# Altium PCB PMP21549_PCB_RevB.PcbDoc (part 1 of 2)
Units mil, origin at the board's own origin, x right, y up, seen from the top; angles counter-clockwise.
Board outline 4798 x 2992 mil, 2 copper layers (Top Layer, Bottom Layer), stack 62 mil thick; 82 components, 39 nets, 178 pads, 21 vias.
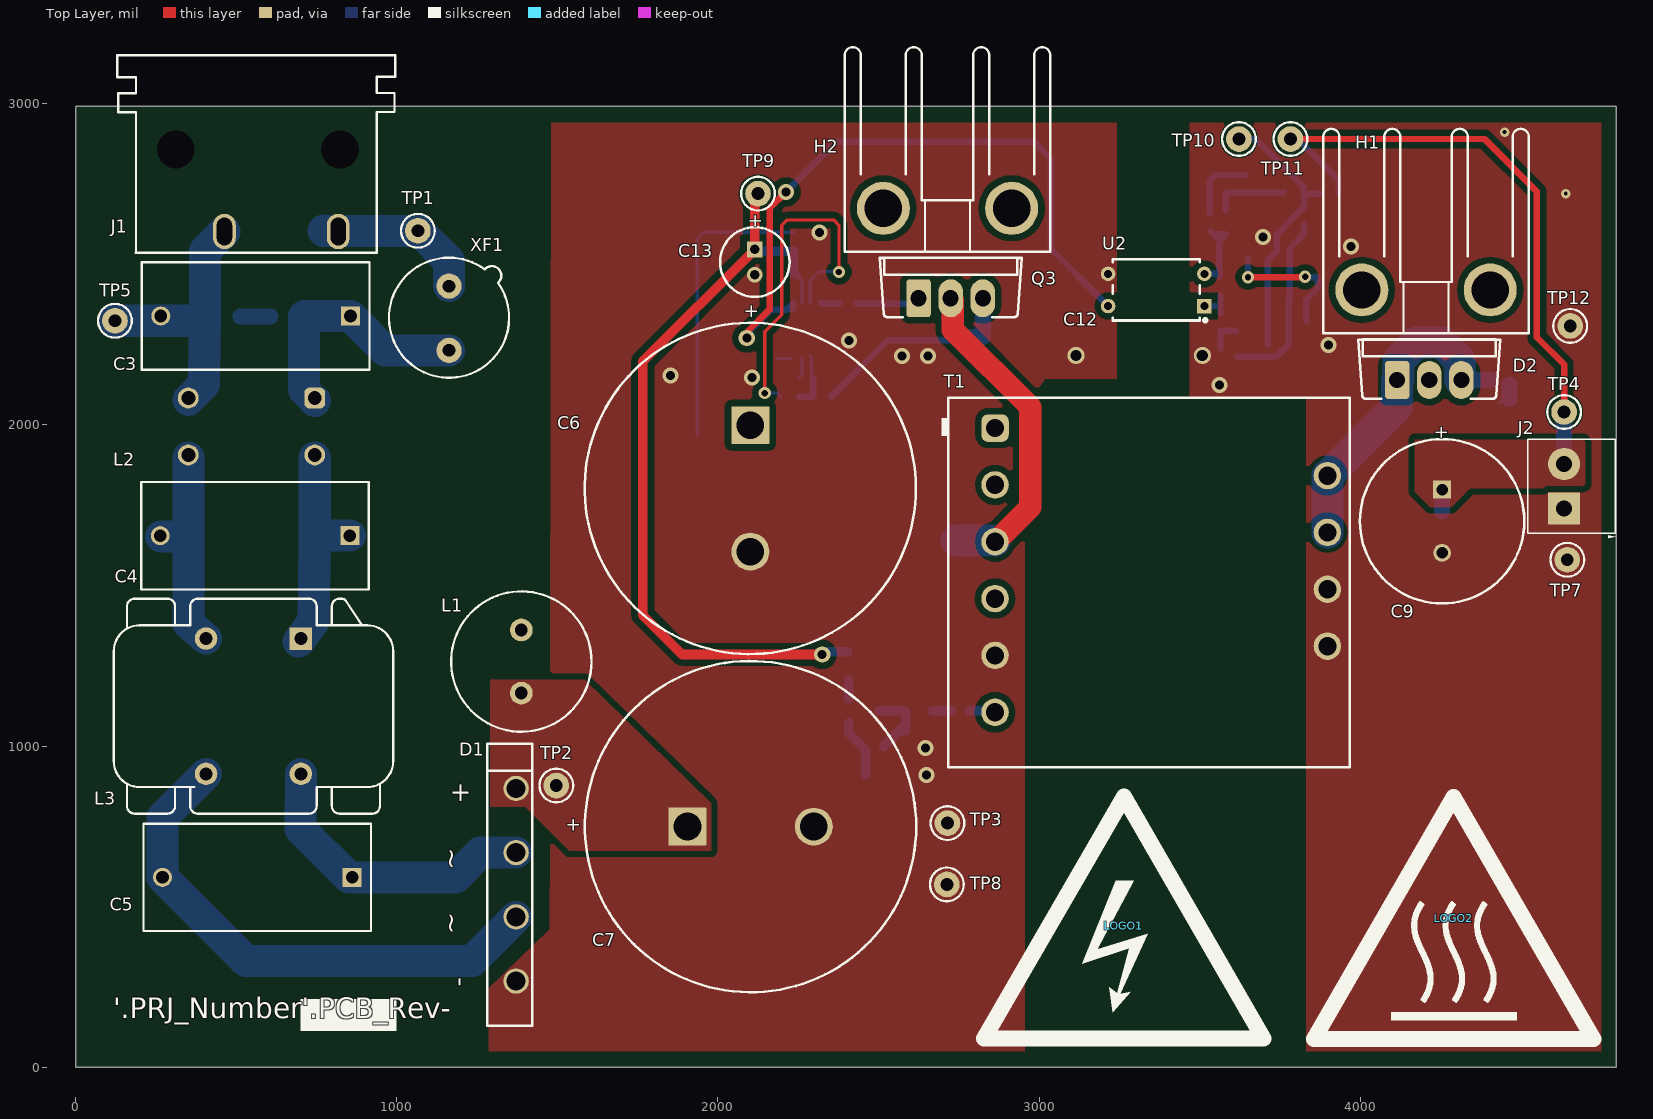
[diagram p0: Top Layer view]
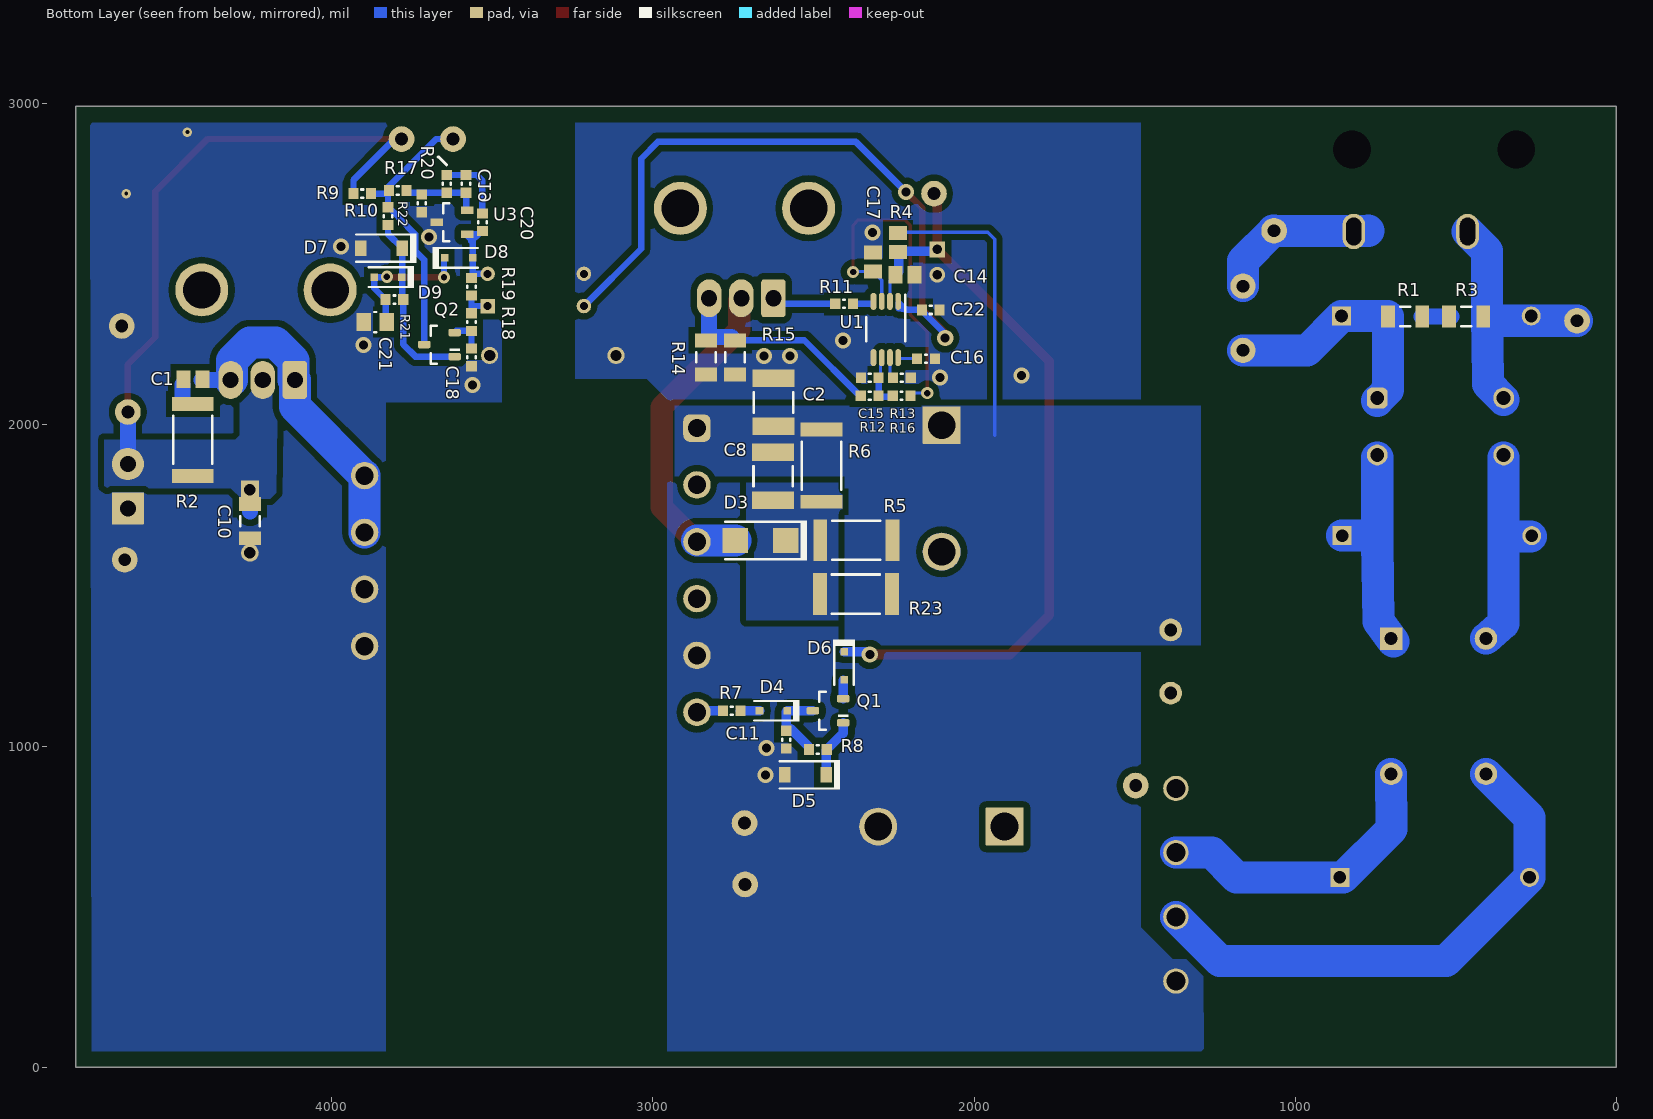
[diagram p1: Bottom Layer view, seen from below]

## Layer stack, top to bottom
Top Solder: solder mask 0.4, Solder Resist, Dk 3.5
Top Layer: signal copper 1.4
Dielectric1: core 59.2, FR-4, Dk 4.8
Bottom Layer: signal copper 1.4
Bottom Solder: solder mask 0.4, Solder Resist, Dk 3.5

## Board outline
0,0 4798,0 4798,2992 0,2992

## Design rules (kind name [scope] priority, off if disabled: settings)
AcuteAngle [All] p1: minimum=4.50000000000000E+0001 checktracksonly=FALSE
AssemblyTestPointUsage [All] p1: valid=2
Clearance Clearance_2 [InNetClass('HV') vs Not InNetClass('HV')] p1: gap=60 ignorepadtopadclearanceinfootprint=FALSE
Clearance Clearance_1 [InNetClass('MV') vs Not InNetClass('MV')] p2: gap=30 ignorepadtopadclearanceinfootprint=FALSE
Clearance Clearance_Keepouts [((IsTrack Or IsArc) And Not InPoly) And IsFree and IsKeepOut vs ((IsTrack Or IsArc) And Not InPoly) And IsFree and IsKeepOut] p3: gap=0 ignorepadtopadclearanceinfootprint=FALSE
Clearance Clearance_BoardEdge_MountingHoles [OnCopper and InComponentClass('Mounting Holes') vs IsKeepOut] p4: gap=40 ignorepadtopadclearanceinfootprint=FALSE except(0: Arc-Hole Track-Hole SMDPad-Hole THPad-Hole Via-Hole Fill-Hole Poly-Hole Region-Hole Text-Hole)
Clearance Clearance_BoardEdge_Poly [OnCopper and InPoly vs IsKeepOut] p5: gap=25 ignorepadtopadclearanceinfootprint=FALSE except(0: Arc-Hole Track-Hole SMDPad-Hole THPad-Hole Via-Hole Fill-Hole Poly-Hole Region-Hole Text-Hole)
Clearance Clearance_BoardEdge [OnCopper and Not InComponentClass('Logo') and not InComponentClass('FiducialMark') and not InRegion(1000,500,4000,800) and Not IsKeepout vs IsKeepOut] p6: gap=75 ignorepadtopadclearanceinfootprint=FALSE except(0: Arc-Hole Track-Hole SMDPad-Hole THPad-Hole Via-Hole Fill-Hole Poly-Hole Region-Hole Text-Hole)
Clearance Clearance_Poly [InPolygon] p7: gap=20 ignorepadtopadclearanceinfootprint=FALSE except(0: Arc-Hole Track-Hole SMDPad-Hole THPad-Hole Via-Hole Fill-Hole Poly-Hole Region-Hole Text-Hole)
Clearance [All] p8: gap=7.87 ignorepadtopadclearanceinfootprint=FALSE except(0: Arc-Hole Track-Hole SMDPad-Hole THPad-Hole Via-Hole Fill-Hole Poly-Hole Region-Hole Text-Hole)
ComponentClearance ComponentClearance_MountingHoles_FiducialMarks [InComponentClass('Mounting Holes') vs InComponentClass('FiducialMark')] p1: gap=20 collisioncheckmode=3 verticalgap=10 showdistances=FALSE
ComponentClearance ComponentClearance_Shunt [InComponentClass('Header') vs InComponentClass('Shunt')] p2: gap=0 collisioncheckmode=3 verticalgap=0 showdistances=FALSE
ComponentClearance ComponentClearance_Logo [InComponentClass('Logo')] p3: gap=5 collisioncheckmode=3 verticalgap=10 showdistances=FALSE
ComponentClearance ComponentClearance_ScrewToNut [(HasFootprint('NY PMS 440 0025 PH')) vs (HasFootprint('Keystone_1902C'))] p4: gap=20 collisioncheckmode=3 verticalgap=100000 showdistances=FALSE
ComponentClearance ComponentClearance_MountingHoles [InComponentClass('Mounting Holes')] p5: gap=20 collisioncheckmode=3 verticalgap=10 showdistances=FALSE
ComponentClearance ComponentClearance_SmallPassives [HasFootprint('0201*') or HasFootprint('0402*') or HasFootprint('0508') or HasFootprint('0603*') or HasFootprint('0612') or HasFootprint('0805*') or HasFootprint('0815*') or HasFootprint('0830*') or HasFootprint('1206*') or HasFootprint('1210*') or HasFootprint('1808*') or HasFootprint('1812*') or HasFootprint('1825*') or HasFootprint('2010*') or HasFootprint('2220*') or HasFootprint('2225*') or HasFootprint('2512*') or HasFootprint('2728*') or HasFootprint('3518*') vs HasFootprint('0201*') or HasFootprint('0402*') or HasFootprint('0508') or HasFootprint('0603*') or HasFootprint('0612') or HasFootprint('0805*') or HasFootprint('0815*') or HasFootprint('0830*') or HasFootprint('1206*') or HasFootprint('1210*') or HasFootprint('1808*') or HasFootprint('1812*') or HasFootprint('1825*') or HasFootprint('2010*') or HasFootprint('2220*') or HasFootprint('2225*') or HasFootprint('2512*') or HasFootprint('2728*') or HasFootprint('3518*')] p6: gap=20 collisioncheckmode=3 verticalgap=20 showdistances=FALSE
ComponentClearance ComponentClearance_THtoSMT [IsThruComponent vs IsSMTComponent] p7: gap=10 collisioncheckmode=3 verticalgap=10 showdistances=FALSE
ComponentClearance ComponentClearance_THtoTH [IsThruComponent vs IsThruComponent] p8: gap=10 collisioncheckmode=3 verticalgap=10 showdistances=FALSE
ComponentClearance [All] p9: gap=10 collisioncheckmode=3 verticalgap=10 showdistances=FALSE
DiffPairsRouting [All] p1: maxlimit=100 minlimit=10 mostfreqgap=10 toplayer_minwidth=15 toplayer_maxwidth=15 toplayer_prefwidth=15 bottomlayer_minwidth=15 bottomlayer_maxwidth=15 bottomlayer_prefwidth=15 maxuncoupledlength=1000
FabricationTestPointUsage TestPointUsage [All] p1: valid=2 allowmultiple=FALSE
FabricationTestpoint Testpoint [All] p1: side=3 testpointundercomponent=TRUE minsize=40 maxsize=100 preferedsize=60 minholesize=0 maxholesize=40 preferedholesize=32 testpointgrid=1 allowsidetop=TRUE allowsidebottom=TRUE usegrid=TRUE gridtolerance=0.01
FanoutControl Fanout_LCC [IsLCC] p1: bgadir=Out bgaviamode=Centered fanoutstyle=Auto fanoutdirection=Alternating viagrid=1 // Fanout_LCC (Default Rule)
FanoutControl Fanout_BGA [IsBGA] p2: bgadir=Out bgaviamode=Centered fanoutstyle=Auto fanoutdirection=Alternating viagrid=1 // Fanout_BGA (Default Rule)
FanoutControl Fanout_Default [All] p4: bgadir=Out bgaviamode=Centered fanoutstyle=Auto fanoutdirection=Alternating viagrid=1 // Fanout_Default (Default Rule)
FanoutControl Fanout_Small [(CompPinCount < 5)] p5: bgadir=Out bgaviamode=Centered fanoutstyle=Auto fanoutdirection=OutThenIn viagrid=1 // Fanout_Small (Default Rule)
Height [All] p1: minheight=0 maxheight=3000 prefheight=500
HoleSize [All] p1: absolutevalues=TRUE maxlimit=251 minlimit=7 maxpercent=80.000 minpercent=20.000
MinimumAnnularRing MinimumAnnularRing_ThermalPadVias [IsVia and InAnyComponent] p1: minimumring=5.91
MinimumAnnularRing [All] p2: minimumring=4.9
MinimumSolderMaskSliver MinimumSolderMaskSliver_Logo [InComponentClass('Logo') vs InComponentClass('Logo')] p1: minsoldermaskwidth=0.7
MinimumSolderMaskSliver [All] p2: minsoldermaskwidth=2
PlaneConnect [All] p1: planeconnectstyle=Direct reliefexpansion=10 reliefentries=4 reliefconductorwidth=10 reliefairgap=10
PolygonConnect PolygonConnect_15 [All vs IsNamedPolygon('C109_2') Or  IsNamedPolygon('C107_2') Or  IsNamedPolygon('HV') Or  IsNamedPolygon('Q203_5') Or  IsNamedPolygon('C107_2') Or  IsNamedPolygon('HS') Or  IsNamedPolygon('Q201_5') Or  IsNamedPolygon('Q203_5') Or  IsNamedPolygon('C106_2') Or  IsNamedPolygon('C108_2') Or  IsNamedPolygon('Vout') Or  IsNamedPolygon('Q203_5') Or  IsNamedPolygon('C108_2') Or  IsNamedPolygon('C113_2') Or  IsNamedPolygon('Q203_5') Or  IsNamedPolygon('Q201_5') Or  IsNamedPolygon('C107_2') Or  IsNamedPolygon('C102_1') Or  IsNamedPolygon('SGND') Or  IsNamedPolygon('GND') Or  IsNamedPolygon('SGND') Or  IsNamedPolygon('GND') Or  IsNamedPolygon('IN+') Or  IsNamedPolygon('IN+') Or  IsNamedPolygon('Q201_5') Or  IsNamedPolygon('Q201_5') Or  IsNamedPolygon('SGND') Or  IsNamedPolygon('SGND') Or  IsNamedPolygon('Vout') Or  IsNamedPolygon('Vout') Or  IsNamedPolygon('IN+') Or  IsNamedPolygon('GND') Or  IsNamedPolygon('IN+') Or  IsNamedPolygon('GND')] p1: connectstyle=Direct reliefconductorwidth=10 reliefentries=4 polygonreliefangle="90 Angle" airgapwidth=10
PolygonConnect PolygonConnect_14 [All vs IsNamedPolygon('C106_2') Or  IsNamedPolygon('C107_2') Or  IsNamedPolygon('C107_2') Or  IsNamedPolygon('C107_2') Or  IsNamedPolygon('C102_1') Or  IsNamedPolygon('Q203_5') Or  IsNamedPolygon('Vout') Or  IsNamedPolygon('Q203_5') Or  IsNamedPolygon('Q203_5') Or  IsNamedPolygon('Q201_5') Or  IsNamedPolygon('C108_2') Or  IsNamedPolygon('Q203_5') Or  IsNamedPolygon('HS') Or  IsNamedPolygon('HV') Or  IsNamedPolygon('C108_2') Or  IsNamedPolygon('Q201_5') Or  IsNamedPolygon('C109_2') Or  IsNamedPolygon('Q201_5') Or  IsNamedPolygon('Q201_5') Or  IsNamedPolygon('C113_2')] p2: connectstyle=Direct reliefconductorwidth=10 reliefentries=4 polygonreliefangle="90 Angle" airgapwidth=10
PolygonConnect PolygonConnect_13 [All vs IsNamedPolygon('C102_1') Or  IsNamedPolygon('HV') Or  IsNamedPolygon('C107_2') Or  IsNamedPolygon('C109_2') Or  IsNamedPolygon('C107_2') Or  IsNamedPolygon('C108_2') Or  IsNamedPolygon('C106_2') Or  IsNamedPolygon('C108_2') Or  IsNamedPolygon('C113_2') Or  IsNamedPolygon('C107_2')] p3: connectstyle=Direct reliefconductorwidth=10 reliefentries=4 polygonreliefangle="90 Angle" airgapwidth=10
PolygonConnect PolygonConnect_12 [All vs IsNamedPolygon('C107_2') Or  IsNamedPolygon('C113_2') Or  IsNamedPolygon('C106_2') Or  IsNamedPolygon('C107_2') Or  IsNamedPolygon('C107_2') Or  IsNamedPolygon('C102_1')] p4: connectstyle=Direct reliefconductorwidth=10 reliefentries=4 polygonreliefangle="90 Angle" airgapwidth=10
PolygonConnect PolygonConnect_11 [All vs IsNamedPolygon('C106_2') Or  IsNamedPolygon('C102_1') Or  IsNamedPolygon('C107_2') Or  IsNamedPolygon('C107_2') Or  IsNamedPolygon('C107_2')] p5: connectstyle=Direct reliefconductorwidth=10 reliefentries=4 polygonreliefangle="90 Angle" airgapwidth=10
PolygonConnect PolygonConnect_10 [All vs IsNamedPolygon('C106_2')] p6: connectstyle=Direct reliefconductorwidth=10 reliefentries=4 polygonreliefangle="90 Angle" airgapwidth=10
PolygonConnect PolygonConnect_9 [All vs IsNamedPolygon('C11_1') Or  IsNamedPolygon('Vin') Or  IsNamedPolygon('Vin') Or  IsNamedPolygon('5V') Or  IsNamedPolygon('D6_2') Or  IsNamedPolygon('Q3_3') Or  IsNamedPolygon('GND2') Or  IsNamedPolygon('GND2') Or  IsNamedPolygon('GND') Or  IsNamedPolygon('Q3_4') Or  IsNamedPolygon('12V5') Or  IsNamedPolygon('GND') Or  IsNamedPolygon('12V5') Or  IsNamedPolygon('D3_1')] p7: connectstyle=Direct reliefconductorwidth=10 reliefentries=4 polygonreliefangle="90 Angle" airgapwidth=10
PolygonConnect PolygonConnect_8 [All vs IsNamedPolygon('C11_1') Or  IsNamedPolygon('Vin') Or  IsNamedPolygon('12V5') Or  IsNamedPolygon('Q3_3') Or  IsNamedPolygon('GND2') Or  IsNamedPolygon('GND2') Or  IsNamedPolygon('5V') Or  IsNamedPolygon('Q3_4') Or  IsNamedPolygon('12V5')] p8: connectstyle=Direct reliefconductorwidth=10 reliefentries=4 polygonreliefangle="90 Angle" airgapwidth=10
PolygonConnect PolygonConnect_7 [All vs IsNamedPolygon('GND2') Or  IsNamedPolygon('GND2') Or  IsNamedPolygon('5V') Or  IsNamedPolygon('12V5') Or  IsNamedPolygon('12V5') Or  IsNamedPolygon('C11_1')] p9: connectstyle=Direct reliefconductorwidth=10 reliefentries=4 polygonreliefangle="90 Angle" airgapwidth=10
PolygonConnect PolygonConnect_6 [All vs IsNamedPolygon('GND2') Or  IsNamedPolygon('SGND') Or  IsNamedPolygon('GND1') Or  IsNamedPolygon('C901_1') Or  IsNamedPolygon('SGND') Or  IsNamedPolygon('GND2') Or  IsNamedPolygon('GND1')] p10: connectstyle=Direct reliefconductorwidth=10 reliefentries=4 polygonreliefangle="90 Angle" airgapwidth=10
PolygonConnect PolygonConnect_5 [All vs IsNamedPolygon('GND1') Or  IsNamedPolygon('GND1')] p11: connectstyle=Direct reliefconductorwidth=10 reliefentries=4 polygonreliefangle="90 Angle" airgapwidth=10
PolygonConnect PolygonConnect_4 [All vs IsNamedPolygon('C21_1') Or  IsNamedPolygon('C5_1') Or  IsNamedPolygon('C12_2') Or  IsNamedPolygon('C2_2') Or  IsNamedPolygon('C13_1') Or  IsNamedPolygon('C28_1') Or  IsNamedPolygon('C6_1') Or  IsNamedPolygon('GND') Or  IsNamedPolygon('GND2') Or  IsNamedPolygon('C14_1') Or  IsNamedPolygon('C13_1') Or  IsNamedPolygon('Q1_3') Or  IsNamedPolygon('C14_1') Or  IsNamedPolygon('C5_1') Or  IsNamedPolygon('GND2') Or  IsNamedPolygon('C28_1') Or  IsNamedPolygon('D5_2') Or  IsNamedPolygon('D6_2') Or  IsNamedPolygon('D2_1') Or  IsNamedPolygon('C12_2') Or  IsNamedPolygon('D2_1') Or  IsNamedPolygon('C4_1') Or  IsNamedPolygon('C4_1') Or  IsNamedPolygon('C2_2') Or  IsNamedPolygon('GND') Or  IsNamedPolygon('C33_1') Or  IsNamedPolygon('C9_1')] p12: connectstyle=Direct reliefconductorwidth=10 reliefentries=4 polygonreliefangle="90 Angle" airgapwidth=10
PolygonConnect PolygonConnect_3 [All vs IsNamedPolygon('C28_1') Or  IsNamedPolygon('C12_2') Or  IsNamedPolygon('C28_1') Or  IsNamedPolygon('C9_1') Or  IsNamedPolygon('D5_2') Or  IsNamedPolygon('C12_2') Or  IsNamedPolygon('C2_2') Or  IsNamedPolygon('C14_1') Or  IsNamedPolygon('C4_1') Or  IsNamedPolygon('C14_1') Or  IsNamedPolygon('D6_2') Or  IsNamedPolygon('GND2') Or  IsNamedPolygon('Q1_3') Or  IsNamedPolygon('C5_1') Or  IsNamedPolygon('D2_1') Or  IsNamedPolygon('C4_1') Or  IsNamedPolygon('C13_1') Or  IsNamedPolygon('C5_1') Or  IsNamedPolygon('C13_1') Or  IsNamedPolygon('C33_1') Or  IsNamedPolygon('D2_1') Or  IsNamedPolygon('GND') Or  IsNamedPolygon('GND') Or  IsNamedPolygon('GND2') Or  IsNamedPolygon('C2_2') Or  IsNamedPolygon('C6_1') Or  IsNamedPolygon('C21_1')] p13: connectstyle=Direct reliefconductorwidth=10 reliefentries=4 polygonreliefangle="90 Angle" airgapwidth=10
PolygonConnect PolygonConnect_2 [All vs IsNamedPolygon('C21_1') Or  IsNamedPolygon('C4_1') Or  IsNamedPolygon('D5_2') Or  IsNamedPolygon('C5_1') Or  IsNamedPolygon('C14_1') Or  IsNamedPolygon('C13_1') Or  IsNamedPolygon('C4_1') Or  IsNamedPolygon('C33_1') Or  IsNamedPolygon('C12_2') Or  IsNamedPolygon('D2_1') Or  IsNamedPolygon('C2_2') Or  IsNamedPolygon('C28_1') Or  IsNamedPolygon('C12_2') Or  IsNamedPolygon('D2_1') Or  IsNamedPolygon('C5_1') Or  IsNamedPolygon('Q1_3') Or  IsNamedPolygon('GND') Or  IsNamedPolygon('D6_2') Or  IsNamedPolygon('C6_1') Or  IsNamedPolygon('C2_2') Or  IsNamedPolygon('C14_1') Or  IsNamedPolygon('C28_1') Or  IsNamedPolygon('C13_1') Or  IsNamedPolygon('C9_1') Or  IsNamedPolygon('GND')] p14: connectstyle=Direct reliefconductorwidth=10 reliefentries=4 polygonreliefangle="90 Angle" airgapwidth=10
PolygonConnect PolygonConnect_1 [All vs IsNamedPolygon('C28_1') Or  IsNamedPolygon('D5_2') Or  IsNamedPolygon('C5_1') Or  IsNamedPolygon('C5_1') Or  IsNamedPolygon('D2_1') Or  IsNamedPolygon('C21_1') Or  IsNamedPolygon('C9_1') Or  IsNamedPolygon('C4_1') Or  IsNamedPolygon('C14_1') Or  IsNamedPolygon('C28_1') Or  IsNamedPolygon('C6_1') Or  IsNamedPolygon('C12_2') Or  IsNamedPolygon('C33_1') Or  IsNamedPolygon('C4_1') Or  IsNamedPolygon('C13_1') Or  IsNamedPolygon('C12_2') Or  IsNamedPolygon('D6_2') Or  IsNamedPolygon('C2_2') Or  IsNamedPolygon('C14_1') Or  IsNamedPolygon('D2_1') Or  IsNamedPolygon('C2_2') Or  IsNamedPolygon('C13_1')] p15: connectstyle=Direct reliefconductorwidth=10 reliefentries=4 polygonreliefangle="90 Angle" airgapwidth=10
PolygonConnect [All] p16: connectstyle=Direct reliefconductorwidth=10 reliefentries=4 polygonreliefangle="90 Angle" airgapwidth=10
RoutingVias ThermalPadVias [IsVia and InAnyComponent] p1: holewidth=7.87 width=19.68 viastyle="Through Hole" minholewidth=7.87 minwidth=19.68 maxholewidth=12.99 maxwidth=23.62
RoutingVias [All] p2: holewidth=16 width=34 viastyle="Through Hole" minholewidth=7.87 minwidth=20 maxholewidth=40 maxwidth=65
SilkToBoardRegionClearance [Not ((IsComment or IsDesignator) And (Hide <> 'False')) and not InRegion(1000,500,4000,800)] p1:
SilkToSilkClearance SilkToSilkClearance_Pb-FreeLogo [(HasFootprint('Pb-Free_Overlay_Medium') OR HasFootprint('Pb-Free_Overlay_Small')) vs (HasFootprint('Pb-Free_Overlay_Medium') OR HasFootprint('Pb-Free_Overlay_Small'))] p1: silktosilkclearance=0
SilkToSilkClearance [All] p2: silktosilkclearance=1
SilkToSolderMaskClearance "Silk to Solder Mask Opening" [All] p1: minsilkscreentomaskgap=1 clearancetoexposedcopper=FALSE
SolderMaskExpansion [All] p1: expansion=1.97
Width [All] p1: maxlimit=100 minlimit=6 preferedwidth=10 checkconnectedcopper=TRUE
14 further rules are at their usual default settings.

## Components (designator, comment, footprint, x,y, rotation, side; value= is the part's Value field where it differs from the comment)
C1 "GRM21AR72E222KW01D" 0805L 4432.47,2142 r180 bottom value=2200pF
C2 "GRM43DR72J104KW01L" 1812L 2625,2070 r90 bottom value=0.1uF
C3 "B32922C3334K" B32922_14.5mm 560.72,2339 r180 top value=0.33uF
C4 "B32922C3334K" B32922_14.5mm 559,1655 r180 top value=0.33uF
C5 "B32922C3334K" B32922_14.5mm 566,591 r180 top value=0.33uF
C6 "LLS2G121MELA" Nichicon_2500x2500_Snap 2101,1802 r270 top value=120uF
C7 "LLS2G121MELA" Nichicon_2500x2500_Snap 2101.85,749 r0 top value=120uF
C8 "GRM43DR72J104KW01L" 1812L 2626,1840 r270 bottom value=0.1uF
C9 "EEU-FR1V102B" FR_1250x2000 4255,1700 r270 top value=1000uF
C10 "C3216X7R1V106K160AC" 1206_180L 4255,1700 r270 bottom value=10uF
C11 "0603YC104JAT2A" 0603L 2585,1020 r270 bottom value=0.1uF
C12 "DE1E3RA222MN4AN01F" DE1_900x400 3312,2216 r180 top value=2200pF
C13 "35ZLJ47MTA5X11" ZLJ_500x1100 2115,2507.01 r270 top value=47uF
C14 "08053D474KAT2A" 0805L 2215,2467.01 r180 bottom value=0.47uF
C15 "06035A271JAT2A" 0603L 2325,2147.01 r0 bottom value=270pF
C16 "C1608X7R1H474K080AC" 0603L 2150,2206 r180 bottom value=0.47uF
C17 "0805YC474JAT2A" 0805L 2315,2507.01 r90 bottom value=0.47uF
C18 "C0603C104J3RACTU" 0603L 3565,2210 r270 bottom value=0.1uF
C19 "C0603C104J3RACTU" 0603L 3582.2,2750.31 r90 bottom value=0.1uF
C20 "C0603X223K5RACTU" 0603L 3531,2631 r270 bottom value=0.022uF
C21 "08053C225KAT2A" 0805_150 3865,2320 r0 bottom value=2.2uF
C22 "06035A101FAT2A" 0603L 2135,2358 r180 bottom value=100pF
D1 "GBU4J-BP" GBU 1372,568 r270 top value=600V
D2 "MBR20200CTTU" TO-220AB 4215,2140 r0 top value=200V
D3 "es1MTR" SMA 2665,1640 r0 bottom value=1000V
D4 "BAS316,115" SOD-323 2625,1110 r0 bottom value=100V
D5 "MMSZ4699T1G" SOD-123 2525,910 r0 bottom value=12V
D6 "BAS316,115" SOD-323 2405,1250 r270 bottom value=100V
D7 "MMSZ5235B-7-F" SOD-123 3845,2550 r0 bottom value=6.8V
D8 "BAS316,115" SOD-323 3605,2520 r180 bottom value=100V
D9 "BAS316,115" SOD-323 3825,2460 r0 bottom value=100V
H1 "634-10ABPE" HSINK_634-10ABP 4205,2420 r0 top
H2 "634-10ABPE" HSINK_634-10ABP 2715,2674.2 r0 top
J1 "770W-X2/10" CONN_AC_770W-SERIES 568,2732 r0 top
J2 "ED555/2DS" TERM_BLK_ED555-2DS 4635,1740 r90 top
L1 "7447471470" WE-TIS-1111 1388,1263 r90 top value=47uH
L2 "744841330" WE-CMB-NiZn-XS 548,1995 r270 top value=30uH
L3 "744823422" WE-CMB_M 554,1124 r270 top value=2.2mH
LOGO1 "DANGER HIGH VOLTAGE" IEC_HighVoltage_Large 3264,441 r0 top
LOGO2 "CAUTION HOT SURFACE" IEC_HotSurface_Large 4291,463 r0 top
Q1 "MMBT3904-7-F" SOT-23 2455,1110 r0 bottom value="40 V"
Q2 "MMBT3904-7-F" SOT-23 3665,2250 r0 bottom value="40 V"
Q3 "SPP17N80C3XKSA1" TO-220AB 2725,2394.2 r0 top value=800V
R1 "CRCW1206499KFKEA" 1206L 657.85,2337 r0 bottom value=499k
R2 "CRCW251220R0FKEG" 2512L 4432.82,1953 r90 bottom value=20.0
R3 "CRCW1206499KFKEA" 1206L 467.85,2337 r0 bottom value=499k
R4 "CRCW0805255KFKEA" 0805L 2236.84,2568 r90 bottom value=255k
R5 "CRCW2512110KJNEG" 2512L 2366.86,1641 r180 bottom value=110k
R6 "CRCW2512110KJNEG" 2512L 2475.37,1872.87 r90 bottom value=110k
R7 "CRCW060310R0FKEA" 0603L 2755,1110 r180 bottom value=10.0
R8 "CRCW060324K9FKEA" 0603L 2486.54,989 r0 bottom value=24.9k
R9 "RMCF0603ZT0R00" 0603L 3905,2720 r0 bottom value=0
R10 "CRCW06035K11FKEA" 0603L 3825,2650 r90 bottom value=5.11k
R11 "CRCW060310R0FKEA" 0603L 2405,2376.7 r0 bottom value=10.0
R12 "RT0603DRE071K07L" 0603L 2325.54,2091 r0 bottom value=1.07k
R13 "CRCW060360K4FKEA" 0603L 2225,2147.01 r0 bottom value=60.4k
R14 "ERJ-8BWFR100V" 1206L 2835,2210 r90 bottom value=0.1
R15 "ERJ-8BWFR100V" 1206L 2745,2210 r90 bottom value=0.1
R16 "CPF0603B100KE" 0603L 2226,2091 r0 bottom value=100k
R17 "RG1608P-2552-B-T5" 0603L 3795,2730 r0 bottom value=25.5k
R18 "CRCW06031K00FKEA" 0603L 3565,2320 r270 bottom value=1.00k
R19 "CRCW06031K00FKEA" 0603L 3565,2430 r270 bottom value=1.00k
R20 "ERJ-3EKF1002V" 0603L 3642.2,2750.31 r270 bottom value=10.0k
R21 "CRCW0603100KFKEA" 0603L 3805,2390 r180 bottom value=100k
R22 "CRCW06032K49FKEA" 0603L 3720,2689.56 r90 bottom value=2.49k
R23 "CRCW2512110KJNEG" 2512L 2368.14,1473 r180 bottom value=110k
T1 "RLTI-1260" Renco_RLTI-1260 3342,1509 r0 top value=1.05mH
TP1 "5000" Keystone5000 1066,2604.25 r90 top
TP2 "5000" Keystone5000 1497,877 r90 top
TP3 "5001" Keystone5001 2715,760 r90 top
TP4 "5000" Keystone5000 4635,2040 r90 top
TP5 "5000" Keystone5000 122.76,2324.25 r90 top
TP7 "5001" Keystone5001 4645,1580 r90 top
TP8 "5001" Keystone5001 2713,569 r90 top
TP9 "5000" Keystone5000 2125,2720 r90 top
TP10 "5000" Keystone5000 3622.6,2890 r90 top
TP11 "5000" Keystone5000 3783,2890 r90 top
TP12 "5001" Keystone5001 4654,2308 r90 top
U1 "LM5021MM-1/NOPB" DGK0008A_N 2275,2297.01 r270 bottom
U2 "FOD817A" DIP-4 3365,2420 r180 top
U3 "TL431AIDBZT" DBZ0003A_N 3626,2631 r0 bottom
XF1 "56000001009" FuseHolder_560000010 1163,2332 r90 top value=TR5

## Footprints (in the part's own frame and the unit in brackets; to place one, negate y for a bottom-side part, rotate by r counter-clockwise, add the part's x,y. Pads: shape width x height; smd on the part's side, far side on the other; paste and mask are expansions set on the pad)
0603L [mm] "0603 from SM-752 data"
  rect 0.8x0.85 smd: 1(-0.7,0) 2(0.7,0)
  silkscreen extent -0.07,-0.33 0.07,0.33, body extent -0.87,-0.47 0.87,0.47, height 1
0805_150 [mm] "0805 / 1.5 mm height"
  rect 1.15x1.45 smd: 1(-0.9,0) 2(0.9,0)
  silkscreen extent -0.1,-0.8 0.1,0.8, body extent -1.1,-0.72 1.1,0.72, height 1.5
0805L [mm] "0805 from SM-752 data"
  rect 1.1x1.4 smd: 1(-0.75,0) 2(0.75,0)
  body extent -1.1,-0.72 1.1,0.72, height 1.45
1206_180L [mm] "1206_180"
  rect 1.1x1.75 smd: 1(-1.35,0) 2(1.35,0)
  silkscreen extent -0.4,-0.77 0.4,0.77, body extent -1.75,-0.95 1.75,0.95, height 1.8
1206L [mm] "1206 from SM-752 data"
  rect 1.1x1.75 smd: 1(-1.35,0) 2(1.35,0)
  silkscreen extent -0.4,-0.77 0.4,0.77, body extent -1.7,-0.9 1.7,0.9, height 1.35
1812L [mm]
  rect 1.4x3.3 smd: 1(-1.9,0) 2(1.9,0)
  silkscreen extent -0.8,-1.55 0.8,1.55, body extent -2.4,-1.7 2.4,1.7, height 1.35
2512L [mm] "Chip Resistor, Body 6.3x3.2mm, IPC High Density"
  rect 1.1x3.3 smd: 1(-2.85,0) 2(2.85,0)
  silkscreen extent -1.9,-1.55 1.9,1.55, body extent -3.22,-1.67 3.22,1.67, height 0.71
B32922_14.5mm [mm] "Epcos film capacitors, 15mm spacing"
  rect 1.5x1.5 hole 1: 1(-7.5,0)
  round 1.5 hole 1: 2(7.5,0)
  silkscreen extent -9,-4.25 9,4.25, body extent -9,-4.25 9,4.25, height 14.5
CONN_AC_770W-SERIES [mm] "Qualtek Electronics"
  oval 1.8x2.8 hole 1.2 slot 2.2 at 90 deg: 1(6.35,-3.3) 2(-2.65,-3.3)
  round 2 hole 3 unplated: MH1(6.5,3.2) MH2(-6.5,3.2)
  silkscreen extent -11.12,-4.97 10.87,10.63, body extent -11.05,-4.8 10.8,10.6, height 22
DBZ0003A_N [mm] "SOT23, 3-Leads, Body 2.9x1.3mm, Pitch 0.95mm, Lead Span 2.4mm, IPC Medium Density"
  rrect17% 1x0.6 smd: 1(-1.2,0.95) 2(-1.2,-0.95) 3(1.2,0)
  silkscreen extent 0.2,-1.5 0.7,1.5, body extent -1.26,-1.46 1.26,1.46, height 0.98
DE1_900x400 [mm] "TH, 2-Leads, Dia 9mm, Lead Spacing 10mm"
  round 1.35 hole 0.9: 1(-5,0) 2(5,0)
  body extent -5.3,-2 5.3,2, height 11.5
DGK0008A_N [mm] "TSOP, 8-Leads, Body 3x3mm, Pitch 0.65mm, IPC Medium Density"
  oval 1.35x0.45 smd: 1(-2.225,0.975) 2(-2.225,0.325) 3(-2.225,-0.325) 4(-2.225,-0.975) 5(2.225,-0.975) 6(2.225,-0.325) 7(2.225,0.325) 8(2.225,0.975)
  silkscreen extent -2.75,-1.55 0.95,1.55, body extent -2.45,-1.5 2.45,1.5, height 0.96
DIP-4 [mm] "DIP, 4-Leads, Body 6.86x4.83mm, Pitch 2.54mm"
  rect 1.15x1.15 hole 0.65: 1(-3.81,1.27)
  round 1.15 hole 0.65: 2(-3.81,-1.27) 3(3.81,-1.27) 4(3.81,1.27)
  silkscreen extent -4,-2.41 3.43,2.52, body extent -4.02,-2.41 4.02,2.41, height 5.59
FR_1250x2000 [mm] "TH, 2-Leads, Dia 12.5mm, Lead Spacing 5mm"
  rect 1.4x1.4 hole 0.9: 1(-2.5,0)
  round 1.4 hole 0.9: 2(2.5,0)
  silkscreen extent -6.5,-6.5 6.5,6.5, body extent -6.45,-6.49 6.49,6.49, height 22.01
FuseHolder_560000010 [mm] "Littelfuse fuse holder TR5"
  round 2 hole 1: 1(-2.54,0) 2(2.54,0)
  silkscreen extent -4.71,-4.75 4.79,4.75, body extent -4.75,-4.74 4.75,4.75, height 5.6
GBU [mm] "Comchip / Diodes Inc diode bridge"
  round 2 hole 1.5: 1(-7.62,0) 2(-2.54,0) 3(2.54,0) 4(7.62,0)
  silkscreen extent -11.15,-2.28 11.15,1.28, body extent -11.15,-2.28 11.15,1.28, height 21.55
HSINK_634-10ABP [mil] "Wakefield"
  round 165 hole 116: MH1(-200,0) MH2(200,0)
  silkscreen extent -320,-135 320,502, body extent -320,-135 320,505, height 1000
IEC_HighVoltage_Large [mil]
  silkscreen extent -435,-352 435,401
IEC_HotSurface_Large [mil]
  silkscreen extent -435,-375 435,378
Keystone5000 [mil] "For Keystone 500x miniature loop terminals"
  round 80 hole 40: 1(0,0)
  silkscreen extent -52,-52 52,52, body extent -49,-49 49,49, height 182
Keystone5001 [mil] "For Keystone 500x miniature loop terminals"
  round 80 hole 40: 1(0,0)
  silkscreen extent -52,-52 52,52, body extent -49,-49 49,49, height 182
Nichicon_2500x2500_Snap [mm]
  rrect3% 3x3 hole 2.2: 1(-5,0)
  round 3 hole 2.2: 2(5,0)
  silkscreen extent -13.1,-13.1 13.1,13.1, body extent -13,-13 13.01,13, height 27.01
Renco_RLTI-1260 [mm] "TH, 10-Leads, Body 1150x1250mil"
  rrect50% 2.175x2.175 hole 1.45: 1(-12.167,12.217)
  round 2.175 hole 1.45: 2(-12.167,7.722) 3(-12.167,3.226) 4(-12.167,-1.27) 5(-12.167,-5.766) 6(-12.167,-10.262) 7(14.122,-5.029) 8(14.122,-0.533) 9(14.122,3.962) 10(14.122,8.458)
  silkscreen extent -16.4,-14.6 15.88,14.6, body extent -15.87,-14.6 15.88,14.61, height 29.21
SMA [mm] "Molded Diode, 2-Leads, Body 4.3x2.6mm, IPC Medium Density, based on OnSemi component dimensions and land pattern"
  rect 2x2 smd: 1(-2,0) 2(2,0)
  silkscreen extent -3.66,-1.57 2.79,1.57, body extent -2.6,-1.3 2.6,1.3, height 2.42
SOD-123 [mm] "On Semi recommended land pattern"
  rect 0.915x1.22 smd: 1(-1.637,0) 2(1.637,0)
  silkscreen extent -2.74,-1.17 2.03,1.17, body extent -1.93,-0.9 1.93,0.9, height 1.35
SOD-323 [mm] "NXP recommended land pattern"
  rect 0.6x0.6 smd paste-0.05: 1(-1.1,0) 2(1.1,0)
  silkscreen extent -2.06,-0.86 1.53,0.86, body extent -1.3,-0.67 1.3,0.68, height 1.1
SOT-23 [mm] "SOT23, 3-Leads, Body 2.9x1.3mm, Pitch 0.95mm, Lead Span 2.5mm, IPC Medium Density"
  rrect50% 1x0.6 smd: 1(-1.2,0.95) 2(-1.2,-0.95) 3(1.2,0)
  silkscreen extent -1.62,-1.5 0.7,1.5, body extent -1.16,-1.45 1.21,1.45, height 1
TERM_BLK_ED555-2DS [mil]
  rrect4% 100x100 hole 50: 1(0,0)
  round 100 hole 50: 2(138,0)
  silkscreen extent -93,-161 215,113, body extent -69,-150 207,106, height 323
TO-220AB [mil] "Copied from Altium's version of TO3B"
  rrect25% 76x118.11 hole 50: 1(-100,0)
  oval 76x118.11 hole 50: 2(0,0) 3(100,0)
  silkscreen extent -221,-59 221,126, body extent -221,-59 221,126, height 765
WE-CMB-NiZn-XS [mm] "TH, 4-Leads, Body 7.5x16mm"
  rrect50% 1.65x1.65 hole 1.1: 1(-2.25,5)
  round 1.65 hole 1.1: 2(2.25,5) 3(2.25,-5) 4(-2.25,-5)
  body extent -3.75,-7.25 3.75,7.25, height 17.35
WE-CMB_M [mil] "Wurth"
  rect 70x70 hole 40: 1(-210.63,147.64)
  round 70 hole 40: 2(-210.63,-147.64) 3(210.63,-147.64) 4(210.63,147.64)
  silkscreen extent -335,-435 335,435, body extent -335,-394 335,394, height 1044
WE-TIS-1111 [mm] "WURTH"
  round 1.8 hole 1.016: 1(-2.5,0) 2(2.5,0)
  silkscreen extent -5.55,-5.55 5.55,5.55, body extent -5.5,-5.5 5.5,5.5, height 11.5
ZLJ_500x1100 [mm] "TH, 2-Leads, Dia 5mm,  Lead Spacing 2mm"
  rect 1.25x1.25 hole 0.75: 1(-1,0)
  round 1.25 hole 0.75: 2(1,0)
  silkscreen extent -2.75,-2.75 2.75,2.75, body extent -2.73,-2.75 2.75,2.75, height 12.51

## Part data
C1: library part CMP-0008253-2, "CAP, CERM, 2200 pF, 250 V, +/- 10%, X7R, 0805", Cap_Case=0805, Manufacturer=MuRata, Supplier Part Number 1=490-3529-1-ND, TempCo=X7R, Tolerance_%=10%, Value1=Unknown, Value2=250V, ValueDisplayed=2200pF
C2 C8: library part CMP-0009455-2, "CAP, CERM, 0.1 uF, 630 V, +/- 10%, X7R, 1812", Cap_Case=1812, Manufacturer=MuRata, Supplier Part Number 1=490-3518-1-ND, TempCo=X7R, Tolerance_%=10%, Value1=Unknown, Value2=630V, ValueDisplayed=0.1uF
C3 C4 C5: library part CMP-0012409-3, "CAP, Film, 0.33 uF, 630 V, +/- 10%, TH", Cap_Case=18x8x14.5mm, Manufacturer=TDK, Supplier Part Number 1=495-5051-ND, Tolerance_%=10%, Value1=Unknown, Value2=630V, ValueDisplayed=0.33uF
C6 C7: library part CMP-0010069-2, "CAP, AL, 120 uF, 400 V, +/- 20%, TH", Cap_Case=25x25mm, Manufacturer=Nichicon, Supplier Part Number 1=493-2570-ND, Tolerance_%=20%, Value1=Unknown, Value2=400V, ValueDisplayed=120uF
C9: library part CMP-0010351-2, "CAP, AL, 1000 uF, 35 V, +/- 20%, 0.018 ohm, TH", Cap_Case=12.5x20mm, Manufacturer=Panasonic, Supplier Part Number 1=P15382CT-ND, Tolerance_%=20%, Value1="0.018 ohm", Value2=35V, ValueDisplayed=1000uF
C10: library part CMP-0008705-2, "CAP, CERM, 10 uF, 35 V, +/- 10%, X7R, 1206", Cap_Case=1206_180, Manufacturer=TDK, Supplier Part Number 1=445-14799-1-ND, TempCo=X7R, Tolerance_%=10%, Value1="0.002229 ohm", Value2=35V, ValueDisplayed=10uF
C11: library part CMP-0006808-4, "CAP, CERM, 0.1 uF, 16 V, +/- 5%, X7R, 0603", Cap_Case=0603, Manufacturer=AVX, Supplier Part Number 1=478-3726-1-ND, TempCo=X7R, Tolerance_%=5%, Value1="0.039 ohm", Value2=16V, ValueDisplayed=0.1uF
C12: library part CMP-0086279-1, "CAP, CERM, 2200 pF, 250 V,+/- 20%, E, Dia 9mm", Cap_Case=9x4mm, Manufacturer=MuRata, TempCo=E, Tolerance_%=20%, Value2=250V, ValueDisplayed=2200pF
C13: library part CMP-0010299-2, "CAP, AL, 47 uF, 35 V, +/- 20%, 0.4 ohm, TH", Cap_Case=5x11mm, Manufacturer=Rubycon, Supplier Part Number 1=1189-1630-1-ND, Tolerance_%=20%, Value1="0.4 ohm", Value2=35V, ValueDisplayed=47uF
C14: library part CMP-0007576-2, "CAP, CERM, 0.47 uF, 25 V, +/- 10%, X5R, 0805", Cap_Case=0805, Manufacturer=AVX, Supplier Part Number 1=478-1407-1-ND, TempCo=X5R, Tolerance_%=10%, Value1="0.017 ohm", Value2=25V, ValueDisplayed=0.47uF
C15: library part CMP-0006779-4, "CAP, CERM, 270 pF, 50 V, +/- 5%, C0G/NP0, 0603", Cap_Case=0603, Manufacturer=AVX, Supplier Part Number 1=478-1180-1-ND, TempCo=C0G/NP0, Tolerance_%=5%, Value1="0.077 ohm", Value2=50V, ValueDisplayed=270pF
C16: library part CMP-0007050-4, "CAP, CERM, 0.47 uF, 50 V, +/- 10%, X7R, 0603", Cap_Case=0603, Manufacturer=TDK, Supplier Part Number 1=445-5952-1-ND, TempCo=X7R, Tolerance_%=10%, Value1="0.010974 ohm", Value2=50V, ValueDisplayed=0.47uF
C17: library part CMP-0007674-2, "CAP, CERM, 0.47 uF, 16 V, +/- 5%, X7R, 0805", Cap_Case=0805, Manufacturer=AVX, Supplier Part Number 1=478-3774-1-ND, TempCo=X7R, Tolerance_%=5%, Value1="0.011 ohm", Value2=16V, ValueDisplayed=0.47uF
C18 C19: library part CMP-0006856-6, "CAP, CERM, 0.1 uF, 25 V, +/- 5%, X7R, 0603", Cap_Case=0603, Manufacturer=Kemet, Supplier Part Number 1=399-1282-1-ND, TempCo=X7R, Tolerance_%=5%, Value1=Unknown, Value2=25V, ValueDisplayed=0.1uF
C20: library part CMP-0006984-4, "CAP, CERM, 0.022 uF, 50 V, +/- 10%, X7R, 0603", Cap_Case=0603, Manufacturer=Kemet, Supplier Part Number 1=399-5340-1-ND, TempCo=X7R, Tolerance_%=10%, Value1=Unknown, Value2=50V, ValueDisplayed=0.022uF
C21: library part CMP-0007573-2, "CAP, CERM, 2.2 uF, 25 V, +/- 10%, X7R, 0805", Cap_Case=0805, Manufacturer=AVX, Supplier Part Number 1=478-5719-1-ND, TempCo=X7R, Tolerance_%=10%, Value1=Unknown, Value2=25V, ValueDisplayed=2.2uF
C22: library part CMP-0006762-4, "CAP, CERM, 100 pF, 50 V, +/- 1%, C0G/NP0, 0603", Cap_Case=0603, Manufacturer=AVX, Supplier Part Number 1=478-6202-1-ND, TempCo=C0G/NP0, Tolerance_%=1%, Value1=Unknown, Value2=50V, ValueDisplayed=100pF
D1: library part CMP-0029241-3, "Diode, P-N-Bridge, 600 V, 4 A, TH", Manufacturer="Micro Commercial Components", Value1=4A, Value2=1V
D2: library part CMP-0077060-2, "Diode, Schottky, 200 V, 10 A, TH", Manufacturer="Fairchild Semiconductor", Supplier Part Number 1=MBR20200CTTU-ND, Value1=10A, Value2=0.9V
D3: library part CMP-0074707-2, "Diode, Superfast Rectifier, 1000 V, 1 A, SMA", Manufacturer="SMC Diode Solutions", Value1=1A, Value2=1.7V
D4 D6 D8 D9: library part CMP-0029006-2, "Diode, Ultrafast, 100 V, 0.25 A, SOD-323", Manufacturer=Nexperia, Value1=0.25A, Value2=1.4V
D5: library part CMP-0005742-4, "Diode, Zener, 12 V, 500 mW, SOD-123", Manufacturer="ON Semiconductor", Power_W=500mW, Value1=0.5W
D7: library part CMP-0005806-3, "Diode, Zener, 6.8 V, 500 mW, SOD-123", Manufacturer="Diodes Inc.", Power_W=500mW, Value1=0.5W
H1 H2: library part CMP-0081782-1, "HEATSINK TO-220 VERT MT BLK 1\"", Manufacturer=Wakefield-Vette, Supplier Part Number 1=345-1130-ND
J1: library part CMP-0074930-1, "AC Receptacle, 2.5A, R/A, TH", Manufacturer="Qualtek Electronics Corporation", Supplier Part Number 1=Q273-ND
J2: library part CMP-0074913-1, "Terminal Block, 3.5mm Pitch, 2x1, TH", Color=Grey, Current_A=6A, Manufacturer="On-Shore Technology", Supplier Part Number 1=ED1514-ND, Voltage_V=150V
L1: library part CMP-0064522-2, "Inductor, Shielded Drum Core, Metal Composite, 47 uH, 2.5 A, 0.074 ohm, TH", Manufacturer="Wurth Elektronik", Supplier Part Number 1=732-3416-ND, Value1="0.074 ohm", Value2=2.5A, ValueDisplayed=47uH
L2: library part CMP-0086201-1, "Coupled inductor, 30 µH, 0.026 ohm, TH", Manufacturer="Wurth Elektronik", ValueDisplayed=30µH
L3: library part CMP-0086200-1, "Coupled inductor, 2.2 mH, 0.03 ohm, TH", Manufacturer="Wurth Elektronik", ValueDisplayed=2.2mH
LOGO1: library part CMP-0074835-1, "IEC 61010-1 High Voltage Warning"
LOGO2: library part CMP-0074837-1, "IEC 61010-1 Hot Surface Warning"
Q1 Q2: library part CMP-0000387-2, "Transistor, NPN, 40 V, 0.2 A, SOT-23", Manufacturer="Diodes Inc.", Supplier Part Number 1=MMBT3904-FDICT-ND, Value1="0.2 A", Value2=400
Q3: library part CMP-0001273-3, "MOSFET, N-CH, 800 V, 17 A, TO-220AB", Alternate Manufacturer=None, Manufacturer="Infineon Technologies", Supplier Part Number 1=SPP17N80C3IN-ND, Value2="64 nC"
R1 R3: library part CMP-0017016-3, "RES, 499 k, 1%, 0.25 W, AEC-Q200 Grade 0, 1206", Manufacturer=Vishay-Dale, Power_W=250mW, Supplier Part Number 1=541-499KFCT-ND, TempCo="100 ppm/C", Tolerance_%=1%, Value2=0.25W, Value_Code=499k
R2: library part CMP-0015531-3, "RES, 20.0, 1%, 1 W, AEC-Q200 Grade 0, 2512", Manufacturer=Vishay-Dale, Power_W=1W, Supplier Part Number 1=541-20.0AFCT-ND, TempCo="100 ppm/C", Tolerance_%=1%, Value_Code=20R0, ValueDisplayed=20.0
R4: library part CMP-0021078-3, "RES, 255 k, 1%, 0.125 W, AEC-Q200 Grade 0, 0805", Manufacturer=Vishay-Dale, Power_W=125mW, Supplier Part Number 1=541-255KCCT-ND, TempCo="100 ppm/C", Tolerance_%=1%, Value2=0.125W, Value_Code=255k
R5 R6 R23: library part CMP-0015871-3, "RES, 110 k, 5%, 1 W, AEC-Q200 Grade 0, 2512", Manufacturer=Vishay-Dale, Power_W=1W, Supplier Part Number 1=541-110KXCT-ND, TempCo="200 ppm/C", Tolerance_%=5%, Value_Code=110k
R7 R11: library part CMP-0022003-3, "RES, 10.0, 1%, 0.1 W, 0603", Manufacturer=Vishay-Dale, Power_W=100mW, Supplier Part Number 1=541-10.0HCT-ND, TempCo="100 ppm/C", Tolerance_%=1%, Value2=0.1W, Value_Code=10R0, ValueDisplayed=10.0
R8: library part CMP-0022237-3, "RES, 24.9 k, 1%, 0.1 W, 0603", Manufacturer=Vishay-Dale, Power_W=100mW, Supplier Part Number 1=541-24.9KHCT-ND, TempCo="100 ppm/C", Tolerance_%=1%, Value2=0.1W, Value_Code=24k9, ValueDisplayed=24.9k
R9: library part CMP-0023343-3, "RES, 0, 1%, 0.1 W, AEC-Q200 Grade 0, 0603", Manufacturer="Stackpole Electronics Inc", Power_W=100mW, Supplier Part Number 1=RMCF0603ZT0R00CT-ND, TempCo=ppm/C, Tolerance_%=1%, Value2=0.1W, Value_Code=0
R10: library part CMP-0022509-3, "RES, 5.11 k, 1%, 0.1 W, 0603", Manufacturer=Vishay-Dale, Power_W=100mW, Supplier Part Number 1=541-5.11KHCT-ND, TempCo="100 ppm/C", Tolerance_%=1%, Value2=0.1W, Value_Code=5k11, ValueDisplayed=5.11k
R12: library part CMP-0024800-3, "RES, 1.07 k, 0.5%, 0.1 W, 0603", Manufacturer="Yageo America", Power_W=100mW, TempCo="50 ppm/C", Tolerance_%=0.5%, Value2=0.1W, Value_Code=1k07, ValueDisplayed=1.07k
R13: library part CMP-0022532-3, "RES, 60.4 k, 1%, 0.1 W, 0603", Manufacturer=Vishay-Dale, Power_W=100mW, Supplier Part Number 1=541-60.4KHCT-ND, TempCo="100 ppm/C", Tolerance_%=1%, Value2=0.1W, Value_Code=60k4, ValueDisplayed=60.4k
R14 R15: library part CMP-0017279-2, "RES, 0.1, 1%, 0.5 W, 1206", Manufacturer=Panasonic, Power_W=500mW, Supplier Part Number 1=1577547, TempCo="150 ppm/C", Tolerance_%=1%, Value2=0.5W, Value_Code=R100, ValueDisplayed=0.1
R16: library part CMP-0023346-3, "RES, 100 k, 0.1%, 0.063 W, 0603", Manufacturer="TE Connectivity", Power_W=63mW, Supplier Part Number 1=279-CPF0603B100KE, TempCo="25 ppm/C", Tolerance_%=0.1%, Value2=0.063W, Value_Code=100k
R17: library part CMP-0023492-3, "RES, 25.5 k, 0.1%, 0.1 W, 0603", Manufacturer="Susumu Co Ltd", Power_W=100mW, Supplier Part Number 1=RG16P25.5KBCT-ND, TempCo="25 ppm/C", Tolerance_%=0.1%, Value2=0.1W, Value_Code=25k5, ValueDisplayed=25.5k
